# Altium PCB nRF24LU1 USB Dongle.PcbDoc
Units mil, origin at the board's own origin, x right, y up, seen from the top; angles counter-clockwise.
Board outline 680 x 441 mil, 4 copper layers (Top Layer, MidLayer1, MidLayer2, Bottom Layer); 30 components, 25 nets, 103 pads, 53 vias.
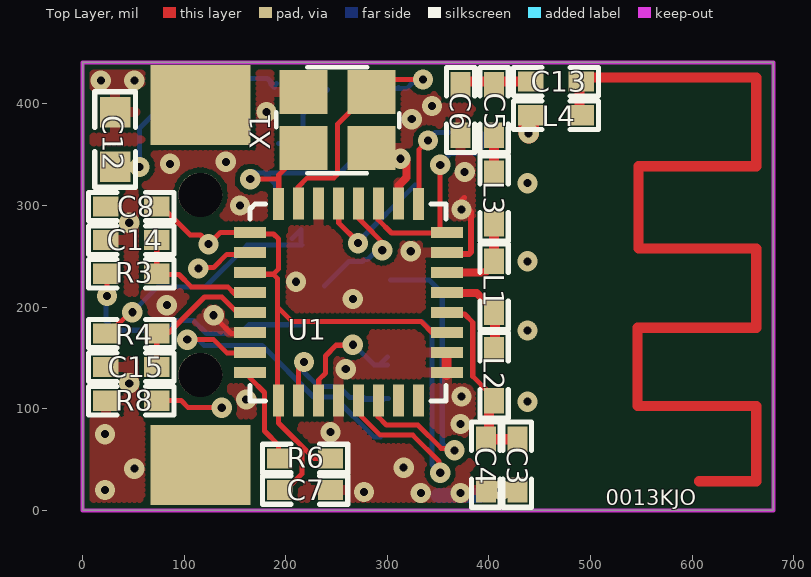
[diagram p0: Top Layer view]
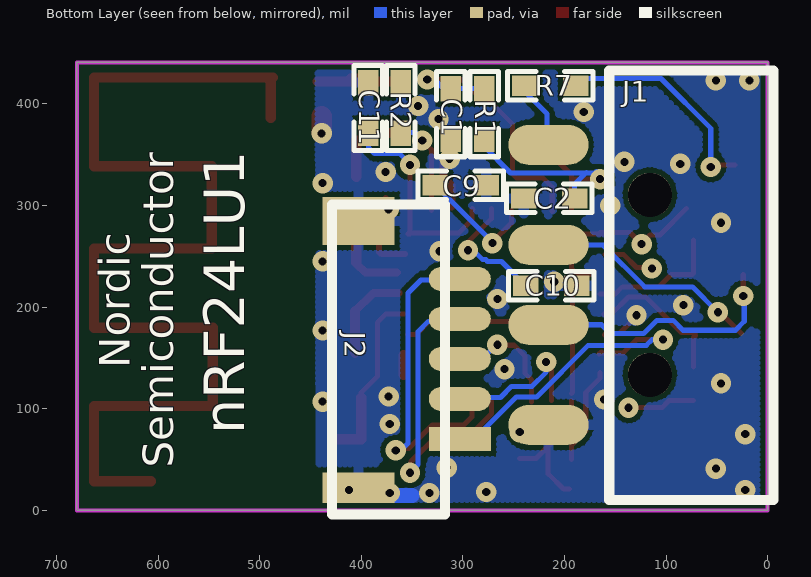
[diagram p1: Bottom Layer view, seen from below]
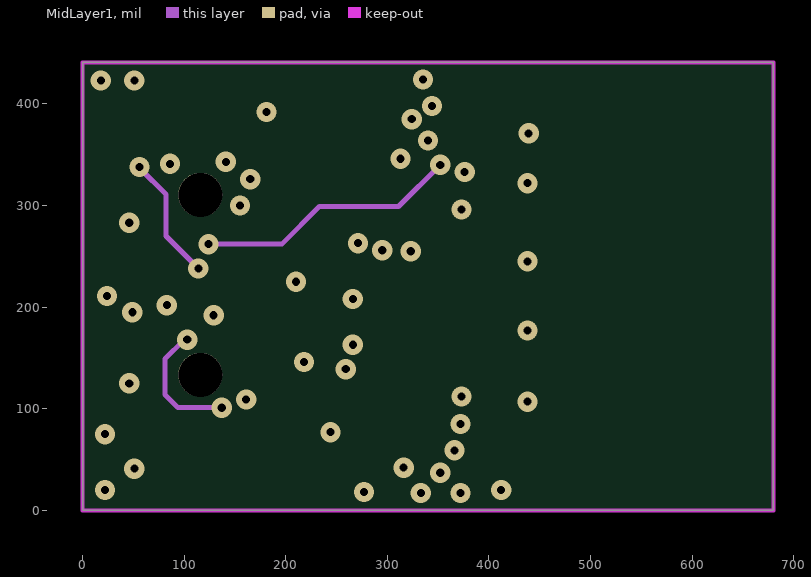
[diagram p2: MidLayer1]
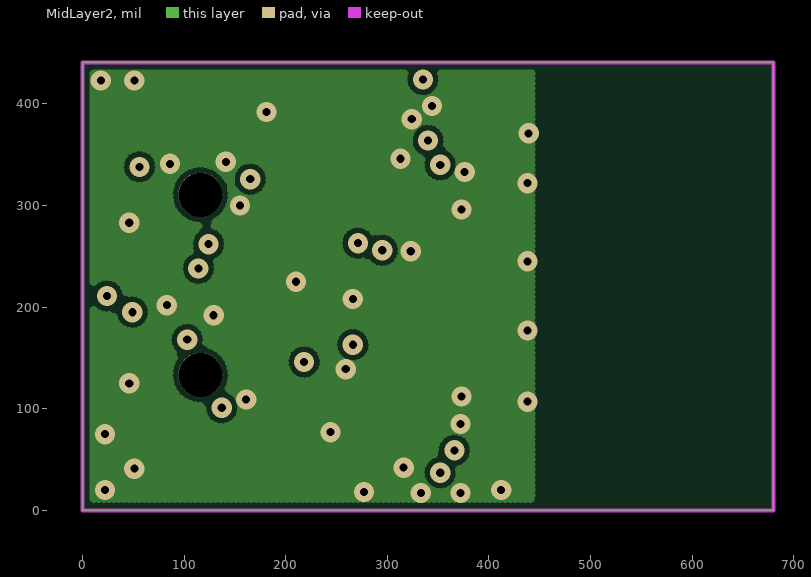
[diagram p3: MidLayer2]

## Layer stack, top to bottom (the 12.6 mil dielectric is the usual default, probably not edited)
Top Layer: signal copper 1.4
Dielectric: prepreg 12.6, FR-4, Dk 4.8
MidLayer1: signal copper 1.4
Dielectric: core 12.6, FR-4, Dk 4.8
MidLayer2: signal copper 1.4
Dielectric: prepreg 12.6, FR-4, Dk 4.8
Bottom Layer: signal copper 1.4

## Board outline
0,0 0,441 680,441 680,0

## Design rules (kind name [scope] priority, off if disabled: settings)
Clearance [All] p1: gap=5
ComponentClearance [All] p1 off: gap=5 collisioncheckmode=3 verticalgap=5
PlaneConnect [(InNet('GND') AND InComponentClass('VIA'))] p1 off: planeconnectstyle=Direct reliefexpansion=20 reliefentries=4 reliefconductorwidth=10 reliefairgap=10
PolygonConnect PolygonConnect_1 [IsVIA and InNET(GND)] p1: connectstyle=Direct reliefconductorwidth=10 reliefentries=4 polygonreliefangle="90 Angle"
PolygonConnect [All] p2: connectstyle=Relief reliefconductorwidth=10 reliefentries=4 polygonreliefangle="90 Angle"
RoomDefinition "nRF24LU1 USB Dongle" [InComponentClass('nRF24LU1 USB Dongle')] p1 off: confinementstyle=ConfineIn formatcopy=TRUE lockcomponents=FALSE outline 744,49 875,49 875,253 744,253
RoutingVias [All] p1: holewidth=8 width=20 viastyle="Through Hole" minholewidth=8 minwidth=20 maxholewidth=28 maxwidth=50
SolderMaskExpansion [All] p1: expansion=4
TestPointUsage [All] p1: valid=0 allowmultiple=FALSE
Testpoint [All] p1: side=15 testpointundercomponent=TRUE minsize=40 maxsize=100 preferedsize=60 minholesize=0 maxholesize=40 preferedholesize=32 testpointgrid=1 style=1023 order=0123456789
Width [All] p1: maxlimit=100 minlimit=5 preferedwidth=10 toplayer_prefwidth=5 midlayer1_prefwidth=5 midlayer2_prefwidth=5 bottomlayer_prefwidth=5 minimp=50.000000 maximp=50.000000 favimp=50.000000
17 further rules are at their usual default settings.

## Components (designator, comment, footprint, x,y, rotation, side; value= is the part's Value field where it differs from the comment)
C1 "NP0 +/-2%" 0402s 312,390 r270 bottom
C2 "NP0 +/-2%" 0402s 215,307 r180 bottom
C3 "X7R +/-10%" 0402s 428,45 r90 top
C4 "NP0 +/-2%" 0402s 397,45 r90 top
C5 "NP0 +/-2%" 0402s 405,394 r270 top
C6 "NP0 +/-2%" 0402s 372,394 r270 top
C7 "X7R +/-10%" 0402s 219,20 r0 top
C8 "X7R +/-10%" 0402s 48,299 r180 top
C9 "X7R, +/-10%" 0402s 302,320 r0 bottom
C10 "X7R, +/-10%" 0402s 213,221 r0 bottom
C11 "X7R +/-10%" 0402s 393,396 r90 bottom
C12 "X5R +/-10%, 6.3v" 0603s 32,365 r90 top
C13 "NP0 +/-2%" 0402s 466,422 r180 top
C14 "NP0 +/-10%" 0402s 48,266 r180 top
C15 "" 0402s 48,141 r180 top
J1 "USB Type A" "ACIN USD SMD" 165,222 r0 bottom
J2 "Digikey 455-1791-1-ND" SH-5 303,149 r90 bottom
L1 "Chip Inductor +/-5%" 0402s 405,220 r270 top
L2 "Chip Inductor +/-5%" 0402s 405,133 r90 top
L3 "Chip Inductor +/-5%" 0402s 405,307 r90 top
L4 "Chip Inductor +/-5%" 0402s 466,389 r0 top
R1 "5%" 0402s 279,390 r270 bottom
R2 "1%" 0402s 361,396 r90 bottom
R3 "5%" 0402s 48,233 r180 top
R4 "5%" 0402s 48,174 r180 top
R6 "5%" 0402s 219,51 r0 top
R7 "5%" 0402s 214,418 r0 bottom
R8 "5%" 0402s 48,108 r180 top
U1 "nRF24LU1" QFN32L/5X5 165,108 r0 top
X1 "FA-20H 16MHz, CL=12pF" "BT-XTAL 2520" 238,385 r180 top

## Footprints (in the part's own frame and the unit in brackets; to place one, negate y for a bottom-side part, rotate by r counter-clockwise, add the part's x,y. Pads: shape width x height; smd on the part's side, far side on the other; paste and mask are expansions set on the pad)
0402s [mil]
  rect 25x20 smd: 1(-25,0) 2(25,0)
  silkscreen extent -42,-14 42,14
0603s [mil]
  rect 30x30 smd: 1(-27,0) 2(27,0)
  silkscreen extent -47,-20 47,20
"ACIN USD SMD" [mm]
  rect 2.5x2 smd far side: 0(-1.246,4.5) 0(-1.246,-4.5)
  oval 2x1 smd: 1(1.288,-3.5) 2(1.288,-1) 3(1.288,1) 4(1.288,3.5)
  round 1.1 hole 1.1 unplated: 6(-1.246,-2.25) 7(-1.246,2.25)
  silkscreen extent -4.34,-5.36 -0.23,5.38
"BT-XTAL 2520" [mm] "TSX-2520"
  rect 1.2x1.1 smd: 1(-1.175,-0.675) 2(0.525,-0.675) 3(0.525,0.725) 4(-1.175,0.725)
  silkscreen extent -1.88,-1.3 1.2,1.35
QFN32L/5X5 [mm]
  rect 0.8x0.28 smd: 1(-0.001,4.205) 2(-0.001,3.705) 3(-0.001,3.205) 4(-0.001,2.705) 5(-0.001,2.205) 6(-0.001,1.705) 7(-0.001,1.205) 8(-0.001,0.705) 17(4.917,0.705) 18(4.917,1.205) 19(4.917,1.705) 20(4.917,2.205) 21(4.917,2.705) 22(4.917,3.205) 23(4.917,3.705) 24(4.917,4.205)
  rect 0.28x0.8 smd: 9(0.71,0) 10(1.21,0.004) 11(1.71,0.004) 12(2.21,0.004) 13(2.71,0.004) 14(3.21,0.004) 15(3.71,0.004) 16(4.21,0.004) 25(4.21,4.921) 26(3.71,4.921) 27(3.21,4.921) 28(2.71,4.921) 29(2.21,4.921) 30(1.71,4.921) 31(1.21,4.921) 32(0.71,4.921)
  silkscreen extent 0,-0.01 4.9,4.92
SH-5 [mm]
  rect 0.6x1.55 smd: 1(-2,0)
  oval 0.6x1.55 smd: 2(-1,0) 3(0,0) 4(1,0) 5(2,0)
  rect 0.762x1.8 smd: 6(-3.219,2.533)
  rect 1.2x1.8 smd: 6(3.448,2.533)
  silkscreen extent -3.89,0.37 3.86,3.19

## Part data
C1 C2 C3 C4 C5 C6 C7 C8 C9 C10 C11 C13 C14 C15: library part CAP
C12: library part "Cap Pol3", "Polarized Capacitor (Surface Mount)"
J1: library part USB_PCB
J2: library part "Header 5", "Header, 5-Pin"
L1 L2 L3 L4: library part INDUCTOR1
R1 R2 R3 R4 R6 R7 R8: library part RES2
U1: library part nRF24Tom, "nRF24 Tomahawk"
X1: library part BT-XTAL

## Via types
v1: diameter 20, hole 8, Top Layer to Bottom Layer, tented both sides, 53 vias

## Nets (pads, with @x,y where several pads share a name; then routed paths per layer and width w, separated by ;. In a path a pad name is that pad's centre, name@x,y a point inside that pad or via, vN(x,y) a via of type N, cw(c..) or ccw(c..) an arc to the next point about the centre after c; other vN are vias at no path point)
CSN: J2.5 U1.14 | length 306.2
  Top Layer w5: U1.14@291,106 291,92 299,84 330,84 353,61 v1@359,61
  Bottom Layer w5: J2.5@303,226.74 341.26,226.74 354,214 354,66 v1@359,61
  other v1: 366,59
GND: C1.2 C2.1 C3.1 C4.1 C6.2 C7.2 C8.2 C9.1 C10.1 C11.2 C12.2 C14.2 C15.2 J1.4 J2.6 L4.1 R2.2 R8.2 U1.6 U1.12 U1.17 U1.18 U1.23 U1.26 U1.30 X1.2 X1.4 | length 251.5
  Top Layer w5: v1@133,186 134,186 146,174 159,174 U1.6@160.55,172.45 ; C6.2 C6.2@372,374 ; v1@373,303 373,305 376,308
  Top Layer w6: U1.23@357,252.21 380.21,252.21 382.5,254.5 382.5,293.5 v1@373,303
  Top Layer w8: U1.26@311.21,299.11 311.21,319.71 319,327.5 v1@319,346
  Top Layer w10: U1.17@358.11,133.1 U1.18@358.11,152.79
  Top Layer w20: v1(439,371) L4.1@439,388
  Bottom Layer w15: 350,14.47 J2.6@391.47,14.47
  other v1: 333,17 372,17 277,18 22,20 412,20 51,41 316,42 22,75 244,77 372,85 438,107 161,109 373,112 46,125 259,139 438,177 129,192 83,202 266,208 210,225 438,245 323,255 46,283 373,296 155,300 438,322 376,333 86,341 141,343 313,346 324,385 181,392 344,398 18,423 51,423
MISO: J2.4 U1.13 | length 308.9
  Top Layer w5: U1.13@271.84,106.89 271.84,95.16 293,74 325,74 351,48 v1@351,35
  Bottom Layer w5: J2.4@305,186 334,186 344,176 344,45 v1(352,37)
MOSI: J2.3 U1.11 | length 136.7
  Top Layer w5: U1.11@232.47,106.89 232.47,128.47 239,135 239,152 249.5,162.5 v1@266.5,162.5 ; v1@264,163 264,160 v1@265,159
  Bottom Layer w5: v1@267,163 287,143 J2.3@300,143 ; J2.3@292,143 J2.3@300,151
  other v1: 266,163
NetC1_1: C1.1 R1.1 U1.31 X1.1 | length 262.9
  Top Layer w5: U1.31@212,294 212,318 221.25,327.25 247.25,327.25 251,331 251,380 X1.1@281,410 ; X1.1@286,409 301,424 v1(335,424)
  Bottom Layer w5: R1.1 310,415 C1.1@311,416 ; C1.1 319,415 325,421
NetC2_2: C2.2 R1.2 U1.32 X1.3 | length 257.5
  Top Layer w5: v1(165,326) 193.1,326 ; U1.32@193.1,295.11 193.1,330.1 X1.3@218,355
  Bottom Layer w5: v1@168.5,333.5 170,332 253,332 279,358 R1.2 ; 178.5,332.5 190,321 C2.2
NetC3_2: C3.2 C4.2 L2.1 U1.20 | length 178.9
  Top Layer w5: U1.20@358.11,193.16 375.84,193.16 384,185 384,132 400,116 L2.1@400,111
  Top Layer w10: L2.1@400,111 400,70 C3.2
NetC5_1: C5.1 C6.1 C13.2 | length 84.6
  Top Layer w10: C6.1@372,422 C13.2@443,422 ; C5.1@398,422 401,425 C5.1@410.32,425
NetC5_2: C5.2 L3.2 | length 36
  Top Layer w10: L3.2@405,328 C5.2@405,364
NetC9_2: C9.2 U1.29 | length 118.7
  Top Layer w5: U1.29@252.16,295.11 252.16,282.84 v1@271,264
  Bottom Layer w5: v1@271,265 272,265 C9.2 C9.2@328,320
  other v1: 271,263
NetC10_2: C10.2 U1.28 | length 121.1
  Top Layer w5: U1.28@272,297 272,287 v1@300,259
  Bottom Layer w5: C10.2 262,245 275.64,245 277.32,246.68 280.53,246.68 289.85,256 v1(295,256)
NetC12_1: C12.1 R7.1 U1.2 | length 404.7
  Top Layer w5: C12.1@32,340 v1@63,340 ; v1@115,240 116,239 129,239 142,252 U1.2@160,252
  MidLayer1 w5: v1@57,336 82,311 82,270 v1@113,239
  Bottom Layer w5: v1(56,338) 56,376 105,425 182,425 R7.1 R7.1@191,420 ; R7.1@185,420 R7.1@189,416
  other v1: 114,238
NetC13_1: C13.1 L4.2 | length 1132.3
  Top Layer w10: C13.1@487,426 663,426 663,338.69 547.11,338.69 547.11,257.68 663,257.68 663,179.68 546.11,179.68 546.11,102.68 663,102.68 663,28.68 607,28.68 ; L4.2@489,386 489,422 C13.1@490,423
NetC14_1: C14.1 R3.1 U1.4 | length 131.9
  Top Layer w5: R3.1 C14.1 ; R3.1@74,232 95,232 107,220 143,220 150,213 U1.4@165,213
NetC15_1: C15.1 R4.1 U1.5 | length 143.4
  Top Layer w5: R4.1@71,172 73,170 C15.1 ; R4.1@71,175 85,175 120,210 137,210 153,194 160,194 U1.5@161,193
NetJ1_1: J1.1 R7.2 | length 86.4
  Bottom Layer w5: J1.1@193,361 J1.1@215,361 ; J1.1@218,360 217,361 217,390 R7.2@241,414
NetJ1_2: J1.2 R4.2 | length 248.8
  Top Layer w5: R4.2@26,174 47,195 v1(49,195)
  Bottom Layer w5: v1@50,196 74,220 121,220 162,261 J1.2@215.71,261 ; J1.2@206.38,267.62 215,276.25 J1.2@215,264
NetJ1_3: J1.3 R3.2 | length 254.3
  Top Layer w5: v1(24,211) R3.2@24,232
  Bottom Layer w5: v1@23,210 23,186 31.75,177.25 83.25,177.25 93,187 109,187 122,174 155,174 163.63,182.63 J1.3
NetL1_1: L1.1 L3.1 U1.22 | length 80.1
  Top Layer w5: U1.22@364,233 U1.22@365,234
  Top Layer w8: U1.22@365,234 396,234 L1.1@405,243
  Top Layer w10: L1.1@405,244 L3.1@405,279
NetL1_2: L1.2 L2.2 U1.21 | length 92.6
  Top Layer w5: U1.21@362.27,213 U1.21@363.27,214
  Top Layer w8: U1.21@363.27,214 388,214 L1.2@406,196
  Top Layer w10: L2.2@406,155 L1.2@406,196
NetR2_1: R2.1 U1.25 | length 110.4
  Top Layer w5: U1.25@330.9,295.11 330.9,308.9 U1.25@331,309 ; U1.25@331,295.11 331,355 v1(340,364)
  Bottom Layer w5: v1@340,365 347,372 R2.1@361,372
NetR6_1: R6.1 U1.8 | length 97.4
  Top Layer w5: U1.8 164.96,130.04 179,116 179,78 193,64 R6.1@193,50
PROG: J2.1 R8.1 U1.7 | length 493.4
  Top Layer w5: R8.1 97,108 104,101 v1(137,101) ; v1(103,168) 129,168 142,155 U1.7@164.96,155 ; U1.7@163.68,156 U1.7@165.89,153.79
  MidLayer1 w5: v1(103,168) 100,168 81,149 81,114 94,101 v1(137,101)
  Bottom Layer w5: v1(103,168) 113.86,168 119.51,162.35 176.65,162.35 227.38,111.62 247.38,111.62 287,72 J2.1@293,72
SCK: J2.2 U1.10 | length 163.8
  Top Layer w5: U1.10 212.64,140.64 v1(218,146)
  Bottom Layer w5: v1(218,146) 218,136 232,122 252,122 263,111 277,111 277,109 296,109 J2.2@297,110 ; J2.2@279,110 J2.2@301,110
VDD: C7.1 C8.1 C11.1 R6.2 U1.1 U1.3 U1.9 U1.19 U1.24 U1.27 | length 1094.7
  Top Layer w5: C8.1@80,297 106,271 116,271 v1@123,264 ; v1(124,262) 135.55,273.55 U1.1 ; U1.1@161.79,273.5 161.79,272 188,272 193,267 193,237.73 187.63,232.37 ; U1.3@171.98,232.37 187.63,232.37 ; U1.9 192.95,86.05 228,51 R6.2 ; U1.9@193,115 192,116 192,228 187.63,232.37 ; 193,199 206,186 333,186 346,173 U1.19@354.58,173 ; C7.1@195,21 201,21 216,36 216,62.16 ; U1.27@290,296 291,297 291,286 304,273 353.01,273 U1.24@354.01,272 ; U1.24@352,272 v1(352,340)
  MidLayer1 w5: v1(124,262) 196,262 233,299 311,299 v1(352,340)
  Bottom Layer w5: v1@127,262 v1@127,263 ; v1@352,341 362,351 387,351 393,357 C11.1
pads on no net: J1.0 J1.6 J1.7 U1.15 U1.16

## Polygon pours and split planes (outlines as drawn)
GND on Top Layer "Top Layer-GND" (hatched 90Degree grid 5 track 7.99, remove dead copper, pour order 1000): -20,439 397,439 397,2 -28,2
GND on MidLayer2 "MidLayer2-GND" (hatched 90Degree grid 5 track 7.99, remove dead copper, pour order 1002): -24,463 442,463 442,-28 -19.71,-28
GND on Bottom Layer "Bottom Layer-GND" (hatched 90Degree grid 5 track 7.99, remove dead copper, pour order 1003): 441,1 -6,1 -6,441 442,441

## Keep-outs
Keep-Out Layer:
  the board outline again, w3.94

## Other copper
Top Layer:
  pour cut-out: 39,179 59,179 59,148 39,148
  pour cut-out: 355,443 355.5,443 349.5,443 349.5,398 383,398 383,0 439,0 439,443
  pour cut-out: 385,287 379,287 379,235 390,235 390,287
  pour cut-out: 193,433 308,433 308,336 302,320 193.1,320

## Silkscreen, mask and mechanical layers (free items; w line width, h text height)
Top Overlay:
  text "0013KJO" at 515,5 h15
Bottom Overlay:
  text "Nordic" at 628,140 h30 r270
  text "nRF24LU1" at 515,75 h40 r270
  text "Semiconductor" at 585,42 h30 r270

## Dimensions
0,0 to 0,441 on Mechanical 1
0,0 to 680,0 on Mechanical 1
